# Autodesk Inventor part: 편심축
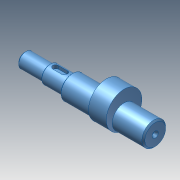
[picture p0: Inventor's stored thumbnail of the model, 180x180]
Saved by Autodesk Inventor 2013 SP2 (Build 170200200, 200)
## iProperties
Created: 2025-04
Part Number: 편심축
Material: Generic
Document SubType Name: Modeling
Designer: i
Density: 1 g/cm^3
Author: i
변환 표준: STEP AP214IS
전처리기: Build: 200, Release: 2013 SP2 Update 6 - Date: Thu 07/17/2014
전송 단위: 밀리미터
불확실성: 0.01
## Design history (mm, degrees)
node "편심축1"
node "솔리드1"
node "기준1"
